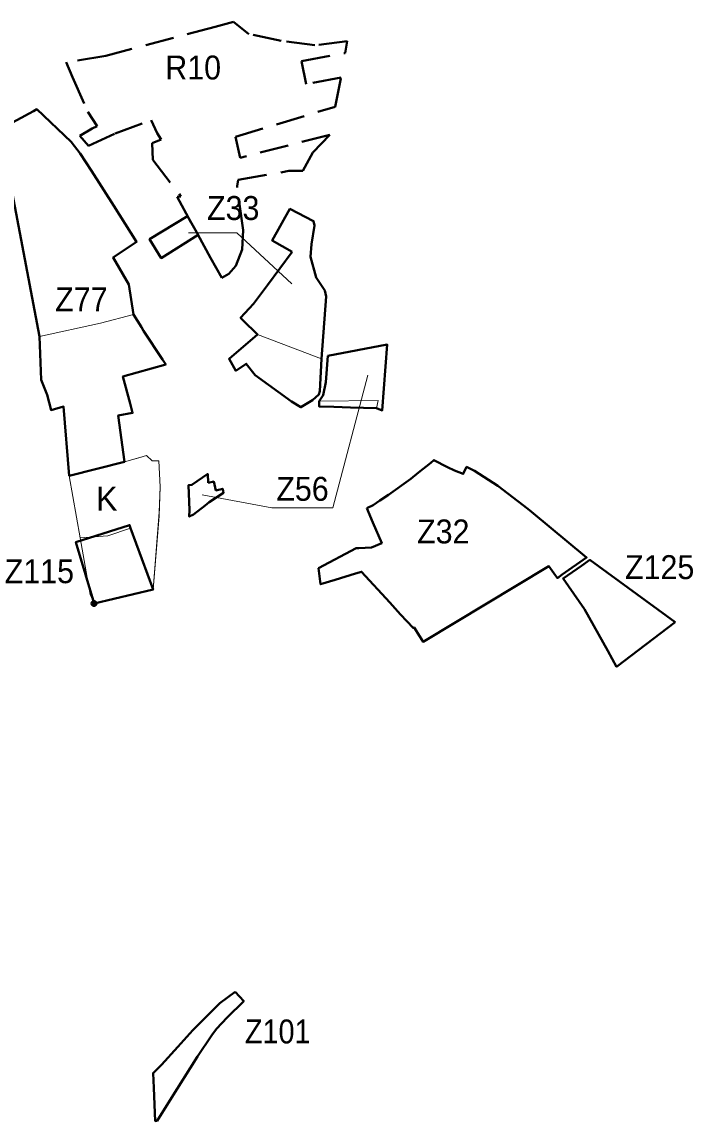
# Model space of a CAD drawing. Extents: x -650276 to -642489, y -1074311 to -1066658.
# Drawn here: x -645192 to -644519, y -1073665 to -1072562 of the extents above; entities that cross this region are included whole.
import ezdxf

# ---------------------------------------------------------------- set-up
doc = ezdxf.new("R2010")
doc.units = 0
doc.header["$LTSCALE"] = 9.6
doc.header["$PDMODE"] = 32
doc.header["$PDSIZE"] = 4.8
doc.linetypes.add('MEDIUM_DASHED', pattern=[4.5, 3, -1.5])
for name, color, linetype, lineweight in [('42', 7, 'Continuous', 25), ('44', 7, 'Continuous', 40), ('45', 7, 'Continuous', 40), ('46', 7, 'Continuous', 13), ('47', 7, 'Continuous', 13), ('48', 7, 'Continuous', 13), ('61', 7, 'MEDIUM_DASHED', 40), ('62', 7, 'Continuous', 35), ('63', 7, 'Continuous', 13)]:
    doc.layers.add(name, color=color, linetype=linetype, lineweight=lineweight)

msp = doc.modelspace()

# ---------------------------------------------------------------- linework, layer by layer
at = {"layer": '42'}
msp.add_lwpolyline([(-644845.72, -1073050.14), (-644839.57, -1073064.5), (-644830.81, -1073084.98), (-644840.89, -1073089.3), (-644853.8, -1073089.99), (-644856.4, -1073090.13), (-644894.15, -1073110.3), (-644892.14, -1073126.36), (-644877.32, -1073121.83), (-644856.97, -1073115.6), (-644851, -1073113.77), (-644822.62, -1073144.71), (-644811.96, -1073156.75), (-644799.26, -1073170.13), (-644798.38, -1073169.56), (-644792.59, -1073178.73), (-644789.31, -1073183.93), (-644663.17, -1073108.27), (-644656.56, -1073117.4), (-644654.61, -1073120.1), (-644649.7, -1073116.65), (-644625.26, -1073099.51), (-644680.69, -1073053.67), (-644684.09, -1073050.8), (-644714.42, -1073027.62), (-644714.42, -1073027.62), (-644737.88, -1073012.62), (-644745.73, -1073008.64), (-644748.95, -1073015.64), (-644757.73, -1073012.05), (-644764.69, -1073008.87), (-644778.38, -1073001.84), (-644781.52, -1073004.39), (-644793.743, -1073014.293), (-644801.54, -1073020.61), (-644824.08, -1073036.56), (-644832.7, -1073042.34), (-644839.47, -1073046.89)], close=True, dxfattribs=at)
at = {"layer": '44'}
msp.add_lwpolyline([(-644977.924, -1073535.072), (-644969.117, -1073544.254), (-644985.66, -1073560.69), (-644996.41, -1073571.97), (-645001.267, -1073578.582), (-645015.55, -1073599.96), (-645043.35, -1073644.04), (-645056.06, -1073664.2), (-645057.87, -1073664.55), (-645059.35, -1073631.3), (-645060.009, -1073616.53), (-645051.513, -1073608.124), (-645035.303, -1073590.199), (-645020.11, -1073573.585), (-644993.044, -1073546.324)], close=True, dxfattribs=at)
at = {"layer": '45'}
for points in [[(-645144.37, -1073017.64), (-645088.62, -1073003.45), (-645095.04, -1072957.07), (-645080.61, -1072954.43), (-645083.13, -1072944.94), (-645090.34, -1072917.86), (-645047.42, -1072906.05), (-645050.6, -1072901.03), (-645069.55, -1072872.12), (-645071.87, -1072868.45), (-645079.81, -1072855.89), (-645084.47, -1072825.67), (-645100.27, -1072798.46), (-645076.66, -1072783.06), (-645099.58, -1072746.945), (-645121.96, -1072711.68), (-645133.26, -1072694.17), (-645142.1, -1072682.57), (-645176.757, -1072649.968), (-645180.05, -1072651.77), (-645213.34, -1072669.98), (-645174.13, -1072877.93), (-645172.28, -1072921.42), (-645166.48, -1072936.5), (-645162.379, -1072951.55), (-645149.84, -1072948.13)], [(-645025.61, -1072757.17), (-645063.6, -1072780.26), (-645051.94, -1072799.21), (-645015.02, -1072776.01)], [(-645025.61, -1072757.17), (-645063.6, -1072780.26), (-645051.94, -1072799.21), (-645015.02, -1072776.01)], [(-644884.94, -1072897.19), (-644886.98, -1072923.48), (-644889.65, -1072936.67), (-644893.37, -1072942.61), (-644893.59, -1072947.97), (-644878.86, -1072948.42), (-644861.93, -1072948.94), (-644835.99, -1072949.74), (-644830.25, -1072951.9), (-644825.25, -1072885.96)], [(-644884.94, -1072897.19), (-644886.98, -1072923.48), (-644889.65, -1072936.67), (-644893.37, -1072942.61), (-644893.59, -1072947.97), (-644878.86, -1072948.42), (-644861.93, -1072948.94), (-644835.99, -1072949.74), (-644830.25, -1072951.9), (-644825.25, -1072885.96)], [(-644845.72, -1073050.14), (-644839.57, -1073064.5), (-644830.81, -1073084.98), (-644840.89, -1073089.3), (-644853.8, -1073089.99), (-644856.4, -1073090.13), (-644894.15, -1073110.3), (-644892.14, -1073126.36), (-644877.32, -1073121.83), (-644856.97, -1073115.6), (-644851, -1073113.77), (-644822.62, -1073144.71), (-644811.96, -1073156.75), (-644799.26, -1073170.13), (-644798.38, -1073169.56), (-644792.59, -1073178.73), (-644789.31, -1073183.93), (-644663.17, -1073108.27), (-644656.56, -1073117.4), (-644654.61, -1073120.1), (-644649.7, -1073116.65), (-644625.26, -1073099.51), (-644680.69, -1073053.67), (-644684.09, -1073050.8), (-644714.42, -1073027.62), (-644714.42, -1073027.62), (-644737.88, -1073012.62), (-644745.73, -1073008.64), (-644748.95, -1073015.64), (-644757.73, -1073012.05), (-644764.69, -1073008.87), (-644778.38, -1073001.84), (-644781.52, -1073004.39), (-644793.743, -1073014.293), (-644801.54, -1073020.61), (-644824.08, -1073036.56), (-644832.7, -1073042.34), (-644839.47, -1073046.89)], [(-644845.72, -1073050.14), (-644839.57, -1073064.5), (-644830.81, -1073084.98), (-644840.89, -1073089.3), (-644853.8, -1073089.99), (-644856.4, -1073090.13), (-644894.15, -1073110.3), (-644892.14, -1073126.36), (-644877.32, -1073121.83), (-644856.97, -1073115.6), (-644851, -1073113.77), (-644822.62, -1073144.71), (-644811.96, -1073156.75), (-644799.26, -1073170.13), (-644798.38, -1073169.56), (-644792.59, -1073178.73), (-644789.31, -1073183.93), (-644663.17, -1073108.27), (-644656.56, -1073117.4), (-644654.61, -1073120.1), (-644649.7, -1073116.65), (-644625.26, -1073099.51), (-644680.69, -1073053.67), (-644684.09, -1073050.8), (-644714.42, -1073027.62), (-644714.42, -1073027.62), (-644737.88, -1073012.62), (-644745.73, -1073008.64), (-644748.95, -1073015.64), (-644757.73, -1073012.05), (-644764.69, -1073008.87), (-644778.38, -1073001.84), (-644781.52, -1073004.39), (-644793.743, -1073014.293), (-644801.54, -1073020.61), (-644824.08, -1073036.56), (-644832.7, -1073042.34), (-644839.47, -1073046.89)], [(-645004.82, -1073024.63), (-645005.31, -1073015.68), (-645021.1, -1073026.69), (-645024.71, -1073026.95), (-645023.6, -1073052.12), (-645023.88, -1073058.37), (-645019.57, -1073056.46), (-645007.99, -1073047.31), (-645003.78, -1073043.96), (-644989.34, -1073034.58), (-644990.25, -1073030.54), (-644997.09, -1073032.21), (-644999.23, -1073023.29)], [(-645004.82, -1073024.63), (-645005.31, -1073015.68), (-645021.1, -1073026.69), (-645024.71, -1073026.95), (-645023.6, -1073052.12), (-645023.88, -1073058.37), (-645019.57, -1073056.46), (-645007.99, -1073047.31), (-645003.78, -1073043.96), (-644989.34, -1073034.58), (-644990.25, -1073030.54), (-644997.09, -1073032.21), (-644999.23, -1073023.29)], [(-645119.34, -1073145.61), (-645060.1, -1073131.68), (-645082.6, -1073069.93), (-645083.681, -1073066.962), (-645137.5, -1073083.97)]]:
    msp.add_lwpolyline(points, close=True, dxfattribs=at)
for points in [[(-644902.18, -1072797.88), (-644901.35, -1072785.36), (-644898.29, -1072766.55), (-644899.2, -1072762.14), (-644922.88, -1072749.97), (-644940.8, -1072781.48), (-644920.46, -1072792.92)], [(-644902.18, -1072797.88), (-644901.35, -1072785.36), (-644898.29, -1072766.55), (-644899.2, -1072762.14), (-644922.88, -1072749.97), (-644940.8, -1072781.48), (-644920.46, -1072792.92)], [(-644920.46, -1072792.92), (-644945.2, -1072826.3), (-644959.24, -1072844.92), (-644972.28, -1072859.02), (-644969.93, -1072861.43), (-644955.49, -1072875.78), (-644983.93, -1072900.24), (-644977.16, -1072912.11), (-644966.57, -1072905.23), (-644957.79, -1072916.73), (-644921.18, -1072943.17), (-644911.87, -1072948.76), (-644900.2, -1072941.67), (-644893.77, -1072935.88), (-644892.86, -1072932.6), (-644891.2, -1072900.09), (-644886.61, -1072837.61), (-644887.99, -1072831.83), (-644896.45, -1072818.78), (-644902.18, -1072797.88)], [(-644920.46, -1072792.92), (-644945.2, -1072826.3), (-644959.24, -1072844.92), (-644972.28, -1072859.02), (-644969.93, -1072861.43), (-644955.49, -1072875.78), (-644983.93, -1072900.24), (-644977.16, -1072912.11), (-644966.57, -1072905.23), (-644957.79, -1072916.73), (-644921.18, -1072943.17), (-644911.87, -1072948.76), (-644900.2, -1072941.67), (-644893.77, -1072935.88), (-644892.86, -1072932.6), (-644891.2, -1072900.09), (-644886.61, -1072837.61), (-644887.99, -1072831.83), (-644896.45, -1072818.78), (-644902.18, -1072797.88)], [(-644536.62, -1073164.33), (-644622.03, -1073101.88), (-644630.58, -1073107.78), (-644648.95, -1073120.47), (-644627.53, -1073151.26)], [(-644627.53, -1073151.26), (-644604.13, -1073193), (-644595.18, -1073208.98), (-644536.62, -1073164.33)]]:
    msp.add_lwpolyline(points, dxfattribs=at)
msp.add_point((-645119.34, -1073145.61), dxfattribs=at)
at = {"layer": '46'}
for points in [[(-645024.402, -1072773.758), (-644975.968, -1072773.758), (-644921.076, -1072825.098)], [(-644844.691, -1072916.725), (-644879.683, -1073049.795), (-644940.921, -1073049.795), (-645010.906, -1073036.663)], [(-644844.691, -1072916.725), (-644879.683, -1073049.795), (-644940.921, -1073049.795), (-645010.906, -1073036.663)]]:
    msp.add_lwpolyline(points, dxfattribs=at)
at = {"layer": '47'}
msp.add_line((-645082.6, -1073069.93), (-645060.1, -1073131.68), dxfattribs=at)
for points in [[(-645060.95, -1073002.68), (-645066.66, -1072997.3), (-645066.66, -1072997.3), (-645074.312, -1072999.359), (-645088.62, -1073003.45)], [(-645060.1, -1073131.68), (-645054.12, -1073057.62), (-645052.94, -1073028.58), (-645054.44, -1073002.54), (-645060.95, -1073002.68)], [(-645088.62, -1073003.45), (-645144.37, -1073017.64), (-645133.18, -1073079.73), (-645105.39, -1073077.58), (-645082.6, -1073069.93)]]:
    msp.add_lwpolyline(points, dxfattribs=at)
at = {"layer": '61'}
msp.add_lwpolyline([(-645107.58, -1072596.47), (-645147.13, -1072602.79), (-645140.96, -1072617.82), (-645125.58, -1072652.42), (-645116.1, -1072667.08), (-645121.26, -1072669.32), (-645133.59, -1072676.49), (-645124.933, -1072686.721), (-645098.016, -1072674.425), (-645062.131, -1072660.856), (-645056.08, -1072674.07), (-645051.87, -1072680.22), (-645061.13, -1072683.98), (-645060.48, -1072700.69), (-645032.11, -1072737.28), (-645036.08, -1072737.88), (-645002.34, -1072799.06), (-644991.3, -1072819.12), (-644984.02, -1072814.87), (-644977, -1072807.06), (-644970.87, -1072790.69), (-644969.63, -1072771.21), (-644975.852, -1072727.059), (-644974.61, -1072720.9), (-644924.08, -1072711.8), (-644909.76, -1072711.64), (-644899.86, -1072693.27), (-644882.85, -1072675.56), (-644972.68, -1072698.65), (-644977.57, -1072677.66), (-644877.32, -1072647.4), (-644871.55, -1072618.07), (-644906.56, -1072624.79), (-644911.21, -1072601.67), (-644867.36, -1072593.58), (-644865.31, -1072581.58), (-644897.87, -1072585.78), (-644931.48, -1072581.26), (-644963.97, -1072574.57), (-644979.55, -1072562.44), (-644997.92, -1072567.23)], close=True, dxfattribs=at)
at = {"layer": '63'}
for p, q in [((-644955.49, -1072875.78), (-644891.2, -1072900.09)), ((-644889.65, -1072936.67), (-644893.37, -1072942.61)), ((-645123.316, -1073136.559), (-645119.34, -1073145.61))]:
    msp.add_line(p, q, dxfattribs=at)
for points in [[(-645176.757, -1072649.968), (-645213.34, -1072669.98), (-645185.613, -1072817.031), (-645185.613, -1072817.031)], [(-645121.96, -1072711.68), (-645133.26, -1072694.17), (-645142.1, -1072682.57), (-645176.757, -1072649.968)], [(-645112.94, -1072864.45), (-645079.81, -1072855.89), (-645084.47, -1072825.67), (-645100.27, -1072798.46), (-645076.66, -1072783.06), (-645121.96, -1072711.68)], [(-644899.2, -1072762.14), (-644922.88, -1072749.97), (-644940.8, -1072781.48), (-644920.46, -1072792.92), (-644945.2, -1072826.3), (-644959.24, -1072844.92), (-644972.28, -1072859.02), (-644969.93, -1072861.43), (-644955.49, -1072875.78)], [(-644891.2, -1072900.09), (-644889.921, -1072882.677), (-644886.61, -1072837.61), (-644887.99, -1072831.83), (-644896.45, -1072818.78), (-644902.18, -1072797.88), (-644901.35, -1072785.36), (-644898.29, -1072766.55), (-644899.2, -1072762.14)], [(-645185.613, -1072817.031), (-645176.639, -1072864.625), (-645176.639, -1072864.625), (-645174.13, -1072877.93), (-645112.94, -1072864.45)], [(-644835.99, -1072949.74), (-644830.25, -1072951.9), (-644825.25, -1072885.96), (-644884.94, -1072897.19), (-644885.12, -1072901.89), (-644886.98, -1072923.48), (-644889.65, -1072936.67)], [(-644893.37, -1072942.61), (-644834.41, -1072942.14), (-644835.99, -1072949.74)], [(-645119.34, -1073145.61), (-645060.1, -1073131.68), (-645053.83, -1073054.04), (-645052.94, -1073028.58), (-645054.44, -1073002.54), (-645060.95, -1073002.68), (-645066.66, -1072997.3), (-645073.23, -1072999.05), (-645088.62, -1073003.45), (-645144.37, -1073017.64)], [(-645144.37, -1073017.64), (-645133.18, -1073079.73), (-645123.316, -1073136.559), (-645123.316, -1073136.559)]]:
    msp.add_lwpolyline(points, dxfattribs=at)

# ---------------------------------------------------------------- texts
at = {"layer": '44', "width": 0.9}
msp.add_text('Z101', height=24, dxfattribs=at).set_placement((-644967.996, -1073586.746))
msp.add_text('Z101', height=24, dxfattribs=at).set_placement((-644967.996, -1073586.746))
at = {"layer": '46', "width": 0.95}
for s, p in [('Z33', (-645005.989, -1072761.006)), ('Z77', (-645158.28, -1072852.64)), ('Z56', (-644936.499, -1073042.592)), ('Z56', (-644936.499, -1073042.592)), ('Z32', (-644795.309, -1073085.354)), ('Z32', (-644795.309, -1073085.354)), ('Z115', (-645208.897, -1073125.218)), ('Z125', (-644586.786, -1073121.127))]:
    msp.add_text(s, height=24, dxfattribs=at).set_placement(p)
at = {"layer": '48'}
msp.add_text('K', height=24, dxfattribs=at).set_placement((-645117.21, -1073052.527))
at = {"layer": '62', "width": 0.95}
msp.add_text('R10', height=24, dxfattribs=at).set_placement((-645047.84, -1072620.116))
msp.add_text('R10', height=24, dxfattribs=at).set_placement((-645047.84, -1072620.116))

doc.saveas('drawing.dxf')
